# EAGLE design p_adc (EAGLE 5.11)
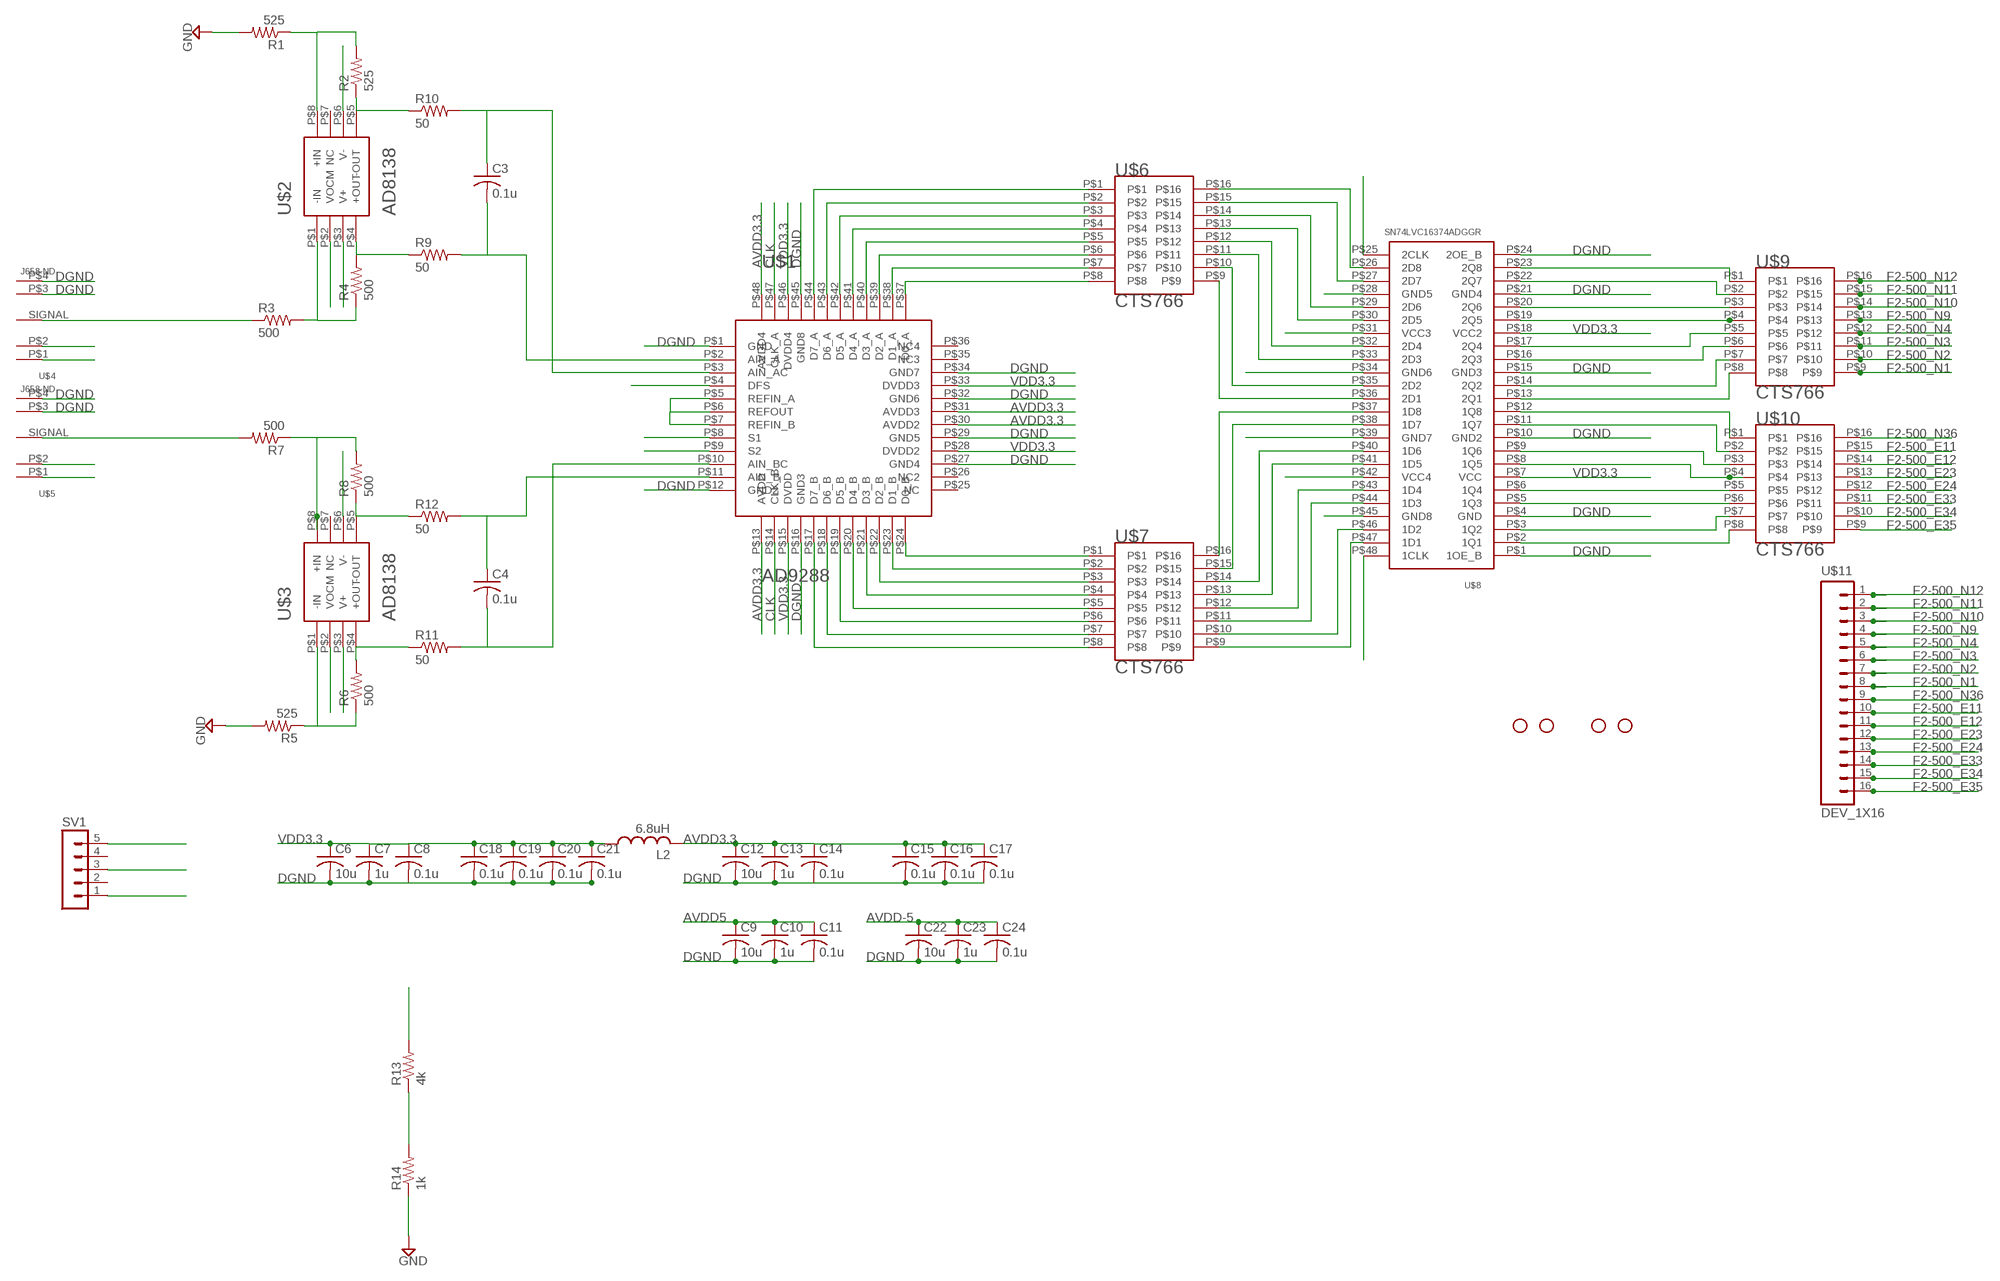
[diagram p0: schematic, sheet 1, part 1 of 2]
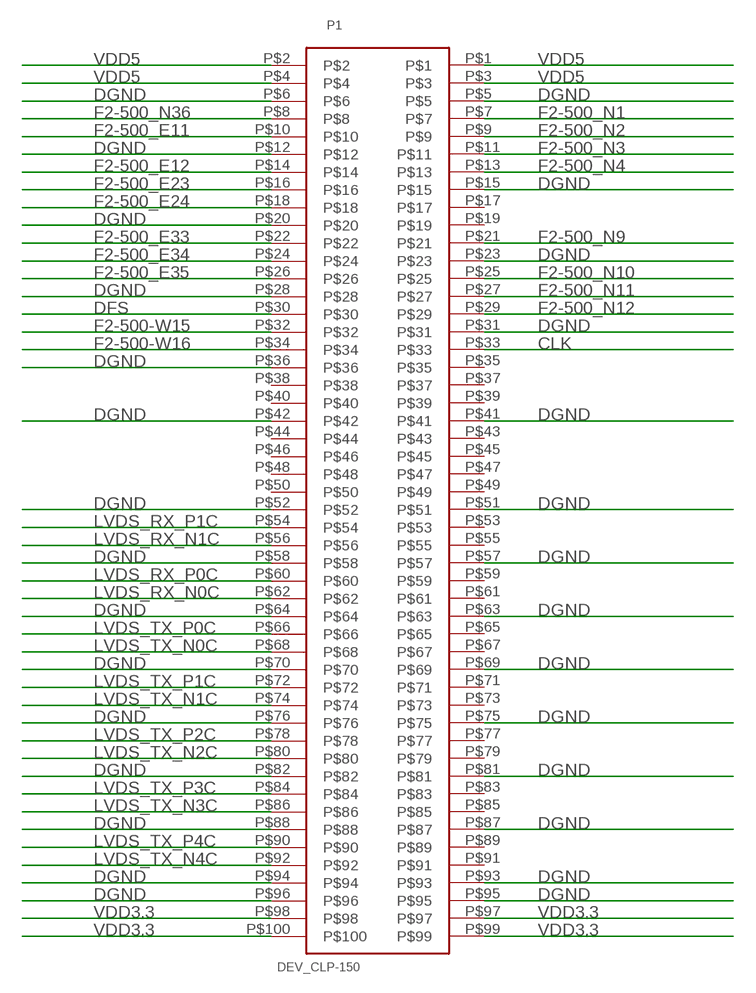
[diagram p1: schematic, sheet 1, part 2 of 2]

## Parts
C3  0.1u  C-USC0603  [C0603]
C4  0.1u  C-USC0603  [C0603]
C6  10u  C-USC0603  [C0603]
C7  1u  C-USC0603  [C0603]
C8  0.1u  C-USC0603  [C0603]
C9  10u  C-USC0603  [C0603]
C10  1u  C-USC0603  [C0603]
C11  0.1u  C-USC0603  [C0603]
C12  10u  C-USC0603  [C0603]
C13  1u  C-USC0603  [C0603]
C14  0.1u  C-USC0603  [C0603]
C15  0.1u  C-USC0603  [C0603]
C16  0.1u  C-USC0603  [C0603]
C17  0.1u  C-USC0603  [C0603]
C18  0.1u  C-USC0603  [C0603]
C19  0.1u  C-USC0603  [C0603]
C20  0.1u  C-USC0603  [C0603]
C21  0.1u  C-USC0603  [C0603]
C22  10u  C-USC0603  [C0603]
C23  1u  C-USC0603  [C0603]
C24  0.1u  C-USC0603  [C0603]
JP1  STAND-OFF  [STAND-OFF]
JP2  STAND-OFF  [STAND-OFF]
JP3  STAND-OFF  [STAND-OFF]
JP4  STAND-OFF  [STAND-OFF]
L2  6.8uH  L-US  [L1210]
P1  DEV_CLP-150  [CLP-150]
R1  525  RESISTOR0603-RES  [0603-RES]
R2  525  RESISTOR0603-RES  [0603-RES]
R3  500  RESISTOR0603-RES  [0603-RES]
R4  500  RESISTOR0603-RES  [0603-RES]
R5  525  RESISTOR0603-RES  [0603-RES]
R6  500  RESISTOR0603-RES  [0603-RES]
R7  500  RESISTOR0603-RES  [0603-RES]
R8  500  RESISTOR0603-RES  [0603-RES]
R9  50  RESISTOR0603-RES  [0603-RES]
R10  50  RESISTOR0603-RES  [0603-RES]
R11  50  RESISTOR0603-RES  [0603-RES]
R12  50  RESISTOR0603-RES  [0603-RES]
R13  4k  RESISTOR0603-RES  [0603-RES]
R14  1k  RESISTOR0603-RES  [0603-RES]
SV1  MA05-1  [MA05-1]
U$1  AD9288  [LQFP(ST-48)]
U$2  AD8138  [MSOP(RM-8)]
U$3  AD8138  [MSOP(RM-8)]
U$4  J658-ND  [SMA-SMD]
U$5  J658-ND  [SMA-SMD]
U$6  CTS766  [16-SOIC]
U$7  CTS766  [16-SOIC]
U$8  SN74LVC16374ADGGR  [TSSOP-48]
U$9  CTS766  [16-SOIC]
U$10  CTS766  [16-SOIC]
U$11  DEV_1X16  [1X16]

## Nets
AVDD3.3: C12.1 C13.1 C14.1 C15.1 C16.1 C17.1 L2.2 U$1.P$13(AVDD) U$1.P$30(AVDD2) U$1.P$31(AVDD3) U$1.P$48(AVDD4)
AVDD5: C9.1 C10.1 C11.1 R13.2 SV1.5 U$2.P$3(V+) U$3.P$3(V+)
AVDD-5: C22.1 C23.1 C24.1 SV1.1 U$2.P$6(V-) U$3.P$6(V-)
CLK: P1.P$33 U$1.P$14(CLK_B) U$1.P$47(CLK_A) U$8.P$25(2CLK) U$8.P$48(1CLK)
DFS: P1.P$30 U$1.P$4(DFS)
DGND: C6.2 C7.2 C8.2 C9.2 C10.2 C11.2 C12.2 C13.2 C14.2 C15.2 C16.2 C17.2 C18.2 C19.2 C20.2 C21.2 C22.2 C23.2 C24.2 P1.P$5 P1.P$6 P1.P$12 P1.P$15 P1.P$20 P1.P$23 P1.P$28 P1.P$31 P1.P$36 P1.P$41 P1.P$42 P1.P$51 P1.P$52 P1.P$57 P1.P$58 P1.P$63 P1.P$64 P1.P$69 P1.P$70 P1.P$75 P1.P$76 P1.P$81 P1.P$82 P1.P$87 P1.P$88 P1.P$93 P1.P$94 P1.P$95 P1.P$96 R1.2 R5.2 R14.1 SV1.3 U$1.P$1(GND) U$1.P$9(S2) U$1.P$12(GND2) U$1.P$16(GND3) U$1.P$27(GND4) U$1.P$29(GND5) U$1.P$32(GND6) U$1.P$34(GND7) U$1.P$45(GND8) U$4.P$1(GND1) U$4.P$2(GND2) U$4.P$3(GND3) U$4.P$4(GND4) U$5.P$1(GND1) U$5.P$2(GND2) U$5.P$3(GND3) U$5.P$4(GND4) U$8.P$1(1OE_B) U$8.P$4(GND) U$8.P$10(GND2) U$8.P$15(GND3) U$8.P$21(GND4) U$8.P$24(2OE_B) U$8.P$28(GND5) U$8.P$34(GND6) U$8.P$39(GND7) U$8.P$45(GND8) ; supply symbol labelled GND
F2-500-W15: P1.P$32
F2-500-W16: P1.P$34
F2-500_E11: P1.P$10 U$10.P$15 U$11.10
F2-500_E12: P1.P$14 U$10.P$14 U$11.11
F2-500_E23: P1.P$16 U$10.P$13 U$11.12
F2-500_E24: P1.P$18 U$10.P$12 U$11.13
F2-500_E33: P1.P$22 U$10.P$11 U$11.14
F2-500_E34: P1.P$24 U$10.P$10 U$11.15
F2-500_E35: P1.P$26 U$10.P$9 U$11.16
F2-500_N1: P1.P$7 U$9.P$9 U$11.8
F2-500_N2: P1.P$9 U$9.P$10 U$11.7
F2-500_N3: P1.P$11 U$9.P$11 U$11.6
F2-500_N4: P1.P$13 U$9.P$12 U$11.5
F2-500_N9: P1.P$21 U$9.P$13 U$11.4
F2-500_N10: P1.P$25 U$9.P$14 U$11.3
F2-500_N11: P1.P$27 U$9.P$15 U$11.2
F2-500_N12: P1.P$29 U$9.P$16 U$11.1
F2-500_N36: P1.P$8 U$10.P$16 U$11.9
LVDS_RX_N0C: P1.P$62
LVDS_RX_N1C: P1.P$56
LVDS_RX_P0C: P1.P$60
LVDS_RX_P1C: P1.P$54
LVDS_TX_N0C: P1.P$68
LVDS_TX_N1C: P1.P$74
LVDS_TX_N2C: P1.P$80
LVDS_TX_N3C: P1.P$86
LVDS_TX_N4C: P1.P$92
LVDS_TX_P0C: P1.P$66
LVDS_TX_P1C: P1.P$72
LVDS_TX_P2C: P1.P$78
LVDS_TX_P3C: P1.P$84
LVDS_TX_P4C: P1.P$90
N$1: R3.2 R4.1 U$2.P$1(-IN)
N$2: R4.2 R9.1 U$2.P$4(+OUT)
N$3: R1.1 R2.2 U$2.P$8(+IN)
N$4: R2.1 R10.1 U$2.P$5(-OUT)
N$5: R6.2 R11.1 U$3.P$4(+OUT)
N$6: R5.1 R6.1 U$3.P$1(-IN)
N$7: R8.1 R12.1 U$3.P$5(-OUT)
N$8: R7.1 R8.2 U$3.P$8(+IN)
N$11: C4.1 R12.2 U$1.P$11(AIN_B)
N$12: C4.2 R11.2 U$1.P$10(AIN_BC)
N$13: R3.1 U$4.SIGNAL
N$14: C3.1 R10.2 U$1.P$3(AIN_AC)
N$15: U$1.P$5(REFIN_A) U$1.P$6(REFOUT) U$1.P$7(REFIN_B)
N$16: U$1.P$24(D0_B) U$7.P$1
N$17: U$1.P$23(D1_B) U$7.P$2
N$18: U$1.P$22(D2_B) U$7.P$3
N$19: U$1.P$21(D3_B) U$7.P$4
N$20: U$1.P$20(D4_B) U$7.P$5
N$21: U$1.P$19(D5_B) U$7.P$6
N$22: U$1.P$18(D6_B) U$7.P$7
N$23: U$1.P$17(D7_B) U$7.P$8
N$24: U$1.P$37(D0_A) U$6.P$8
N$25: U$1.P$38(D1_A) U$6.P$7
N$26: U$1.P$39(D2_A) U$6.P$6
N$27: U$1.P$40(D3_A) U$6.P$5
N$28: U$1.P$41(D4_A) U$6.P$4
N$29: U$1.P$42(D5_A) U$6.P$3
N$30: U$1.P$43(D6_A) U$6.P$2
N$31: U$1.P$44(D7_A) U$6.P$1
N$32: C3.2 R9.2 U$1.P$2(AIN_A)
N$33: R7.2 U$5.SIGNAL
N$34: U$8.P$13(2Q1) U$9.P$8
N$35: U$6.P$9 U$8.P$36(2D1)
N$36: U$6.P$10 U$8.P$35(2D2)
N$37: U$6.P$11 U$8.P$33(2D3)
N$38: U$6.P$12 U$8.P$32(2D4)
N$39: U$6.P$13 U$8.P$30(2D5)
N$40: U$6.P$14 U$8.P$29(2D6)
N$41: U$6.P$15 U$8.P$27(2D7)
N$42: U$6.P$16 U$8.P$26(2D8)
N$43: U$7.P$16 U$8.P$37(1D8)
N$44: U$7.P$15 U$8.P$38(1D7)
N$45: U$7.P$14 U$8.P$40(1D6)
N$46: U$7.P$13 U$8.P$41(1D5)
N$47: U$7.P$12 U$8.P$43(1D4)
N$48: U$7.P$11 U$8.P$44(1D3)
N$49: U$7.P$10 U$8.P$46(1D2)
N$50: U$7.P$9 U$8.P$47(1D1)
N$51: U$8.P$14(2Q2) U$9.P$7
N$52: U$8.P$16(2Q3) U$9.P$6
N$53: U$8.P$17(2Q4) U$9.P$5
N$54: U$8.P$19(2Q5) U$9.P$4
N$55: U$8.P$20(2Q6) U$9.P$3
N$56: U$8.P$23(2Q8) U$9.P$1
N$57: U$8.P$22(2Q7) U$9.P$2
N$58: U$8.P$2(1Q1) U$10.P$8
N$59: U$8.P$3(1Q2) U$10.P$7
N$60: U$8.P$5(1Q3) U$10.P$6
N$61: U$8.P$6(1Q4) U$10.P$5
N$62: U$8.P$12(1Q8) U$10.P$1
N$63: U$8.P$11(1Q7) U$10.P$2
N$64: U$8.P$9(1Q6) U$10.P$3
N$65: U$8.P$8(1Q5) U$10.P$4
VCOM: R13.1 R14.2 U$2.P$2(VOCM) U$3.P$2(VOCM)
VDD3.3: C6.1 C7.1 C8.1 C18.1 C19.1 C20.1 C21.1 L2.1 P1.P$97 P1.P$98 P1.P$99 P1.P$100 U$1.P$8(S1) U$1.P$15(DVDD) U$1.P$28(DVDD2) U$1.P$33(DVDD3) U$1.P$46(DVDD4) U$8.P$7(VCC) U$8.P$18(VCC2) U$8.P$31(VCC3) U$8.P$42(VCC4)
VDD5: P1.P$1 P1.P$2 P1.P$3 P1.P$4
Unconnected: P1.P$17 P1.P$19 P1.P$35 P1.P$37 P1.P$38 P1.P$39 P1.P$40 P1.P$43 P1.P$44 P1.P$45 P1.P$46 P1.P$47 P1.P$48 P1.P$49 P1.P$50 P1.P$53 P1.P$55 P1.P$59 P1.P$61 P1.P$65 P1.P$67 P1.P$71 P1.P$73 P1.P$77 P1.P$79 P1.P$83 P1.P$85 P1.P$89 P1.P$91 SV1.2 SV1.4 U$1.P$25(NC) U$1.P$26(NC2) U$1.P$35(NC3) U$1.P$36(NC4) U$2.P$7(NC) U$3.P$7(NC)

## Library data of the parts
C3 C4 C6-C24 = rcl:C-US: CAPACITOR, American symbol
JP1-JP4 = SparkFun:STAND-OFF: Stand Off
L2 = sam:L-US: INDUCTOR, American symbol
P1 = EECS370:DEV_CLP-150
R1-R14 = SparkFun:RESISTOR: Resistor
SV1 = con-lstb:MA05-1: PIN HEADER; OC_FARNELL: unknown; OC_NEWARK: unknown
U$1 = sam:AD9288
U$2 U$3 = sam:AD8138
U$4 U$5 = sam:J658-ND
U$6 U$7 U$9 U$10 = sam:CTS766
U$8 = sam:SN74LVC16374ADGGR
U$11 = EECS370:DEV_1X16

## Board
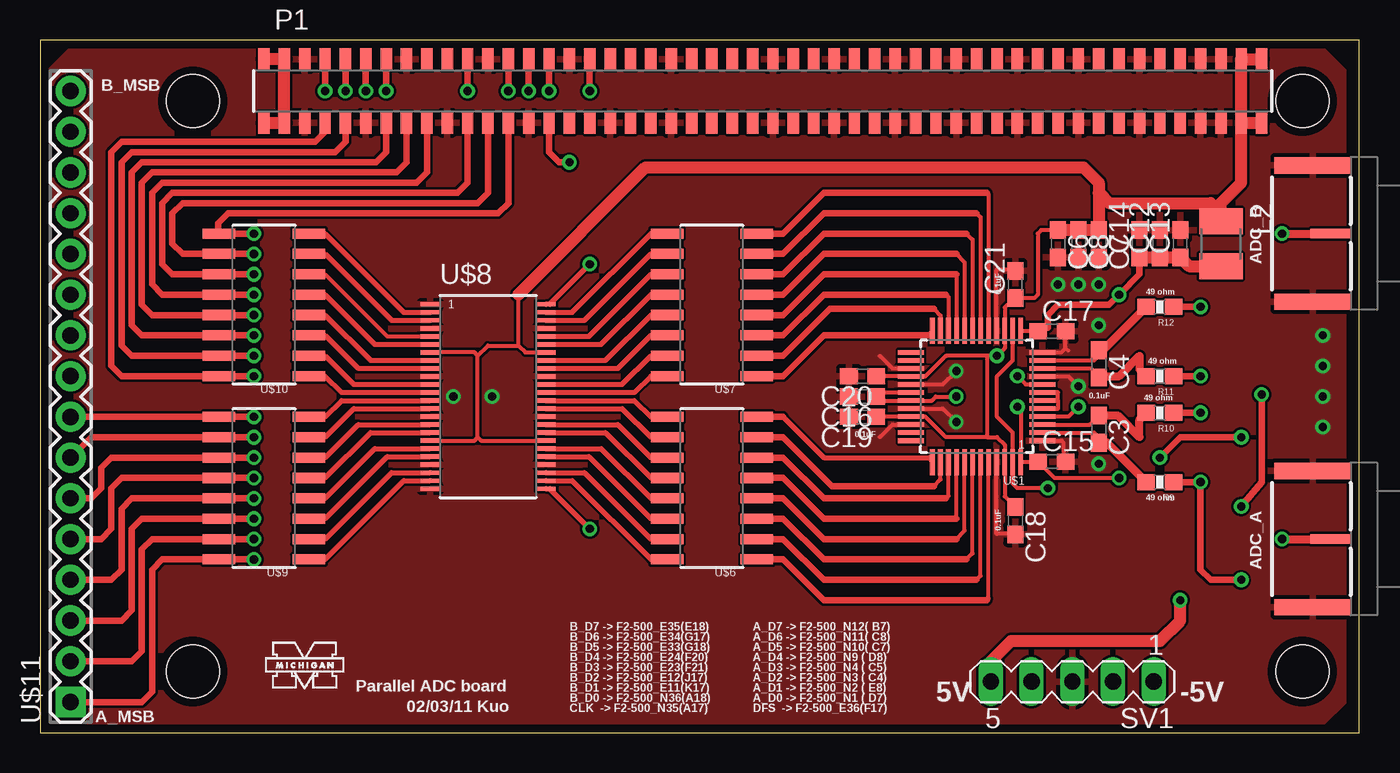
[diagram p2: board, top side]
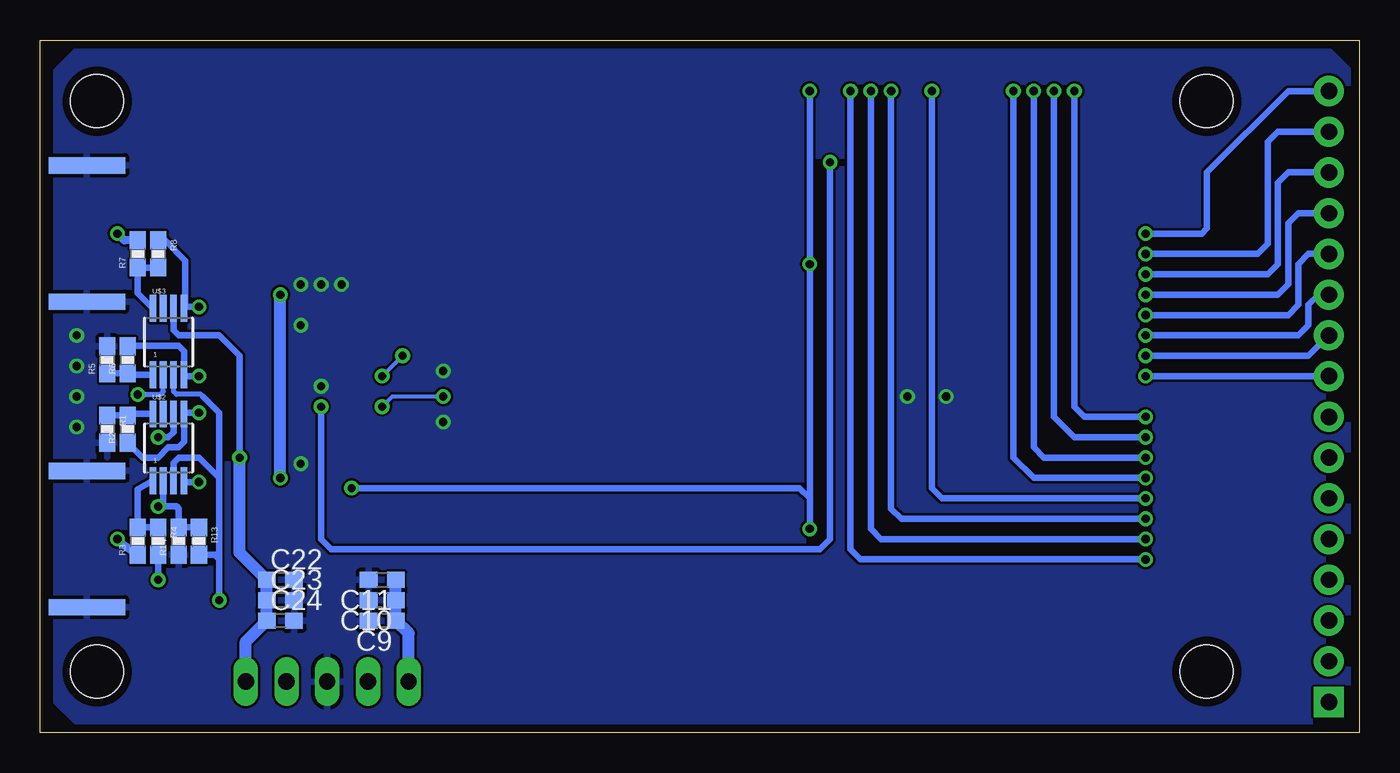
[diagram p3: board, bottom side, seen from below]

Size 82.3 x 43.18 mm. Coordinates in mm from the lower left corner, seen from the top.
Outline: 0,0 82.3,0 82.3,43.18 0,43.18 0,0
Copper layers (1*16): Top 0.0178mm / dielectric 1.4986mm / Bottom 0.0178mm
Design rules "SSC-EAGLE-2Lyr_v1.0.0.3": minimum track width 6mil, minimum drill 14mil, track to track 6mil, track to pad 6mil, pad to pad 6mil, via to via 6mil, smd to smd 6mil, copper to edge 20mil, drill to drill 16mil, minimum pad ring 8mil, minimum via ring 8mil, stop-mask expansion 3mil, vias tented up to drill 0mil, thermal gap 10mil

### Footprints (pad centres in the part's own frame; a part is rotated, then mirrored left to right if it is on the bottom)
C0603 = smd 1.1 x 1: 1 -0.85,0; 2 0.85,0
STAND-OFF = hole 3.302: 0,0
L1210 = smd 1.6 x 2.7: 1 -1.4,0; 2 1.4,0
CLP-150 = smd 0.711 x 1.35: P$1 -31.115,1.99; P$2 -31.115,-1.99; P$3 -29.845,1.99; P$4 -29.845,-1.99; P$5 -28.575,1.99; P$6 -28.575,-1.99; P$7 -27.305,1.99; P$8 -27.305,-1.99; P$9 -26.035,1.99; P$10 -26.035,-1.99; P$11 -24.765,1.99; P$12 -24.765,-1.99; P$13 -23.495,1.99; P$14 -23.495,-1.99; P$15 -22.225,1.99; P$16 -22.225,-1.99; P$17 -20.955,1.99; P$18 -20.955,-1.99; P$19 -19.685,1.99; P$20 -19.685,-1.99; P$21 -18.415,1.99; P$22 -18.415,-1.99; P$23 -17.145,1.99; P$24 -17.145,-1.99; P$25 -15.875,1.99; P$26 -15.875,-1.99; P$27 -14.605,1.99; P$28 -14.605,-1.99; P$29 -13.335,1.99; P$30 -13.335,-1.99; P$31 -12.065,1.99; P$32 -12.065,-1.99; P$33 -10.795,1.99; P$34 -10.795,-1.99; P$35 -9.525,1.99; P$36 -9.525,-1.99; P$37 -8.255,1.99; P$38 -8.255,-1.99; P$39 -6.985,1.99; P$40 -6.985,-1.99; P$41 -5.715,1.99; P$42 -5.715,-1.99; P$43 -4.445,1.99; P$44 -4.445,-1.99; P$45 -3.175,1.99; P$46 -3.175,-1.99; P$47 -1.905,1.99; P$48 -1.905,-1.99; P$49 -0.635,1.99; P$50 -0.635,-1.99; P$51 0.635,1.99; P$52 0.635,-1.99; P$53 1.905,1.99; P$54 1.905,-1.99; P$55 3.175,1.99; P$56 3.175,-1.99; P$57 4.445,1.99; P$58 4.445,-1.99; P$59 5.715,1.99; P$60 5.715,-1.99; P$61 6.985,1.99; P$62 6.985,-1.99; P$63 8.255,1.99; P$64 8.255,-1.99; P$65 9.525,1.99; P$66 9.525,-1.99; P$67 10.795,1.99; P$68 10.795,-1.99; P$69 12.065,1.99; P$70 12.065,-1.99; P$71 13.335,1.99; P$72 13.335,-1.99; P$73 14.605,1.99; P$74 14.605,-1.99; P$75 15.875,1.99; P$76 15.875,-1.99; P$77 17.145,1.99; P$78 17.145,-1.99; P$79 18.415,1.99; P$80 18.415,-1.99; P$81 19.685,1.99; P$82 19.685,-1.99; P$83 20.955,1.99; P$84 20.955,-1.99; P$85 22.225,1.99; P$86 22.225,-1.99; P$87 23.495,1.99; P$88 23.495,-1.99; P$89 24.765,1.99; P$90 24.765,-1.99; P$91 26.035,1.99; P$92 26.035,-1.99; P$93 27.305,1.99; P$94 27.305,-1.99; P$95 28.575,1.99; P$96 28.575,-1.99; P$97 29.845,1.99; P$98 29.845,-1.99; P$99 31.115,1.99; P$100 31.115,-1.99
0603-RES = smd 1.1 x 1: 1 -0.85,0; 2 0.85,0
MA05-1 = drill 1.016 long: 1 -5.08,0; 2 -2.54,0; 3 0,0; 4 2.54,0; 5 5.08,0
LQFP(ST-48) = smd 1.6 x 0.3: P$1 -4.1,2.75; P$2 -4.1,2.25; P$3 -4.1,1.75; P$4 -4.1,1.25; P$5 -4.1,0.75; P$6 -4.1,0.25; P$7 -4.1,-0.25; P$8 -4.1,-0.75; P$9 -4.1,-1.25; P$10 -4.1,-1.75; P$11 -4.1,-2.25; P$12 -4.1,-2.75; P$25 4.1,-2.75; P$26 4.1,-2.25; P$27 4.1,-1.75; P$28 4.1,-1.25; P$29 4.1,-0.75; P$30 4.1,-0.25; P$31 4.1,0.25; P$32 4.1,0.75; P$33 4.1,1.25; P$34 4.1,1.75; P$35 4.1,2.25; P$36 4.1,2.75 | smd 0.3 x 1.6: P$13 -2.75,-4.1; P$14 -2.25,-4.1; P$15 -1.75,-4.1; P$16 -1.25,-4.1; P$17 -0.75,-4.1; P$18 -0.25,-4.1; P$19 0.25,-4.1; P$20 0.75,-4.1; P$21 1.25,-4.1; P$22 1.75,-4.1; P$23 2.25,-4.1; P$24 2.75,-4.1; P$37 2.75,4.1; P$38 2.25,4.1; P$39 1.75,4.1; P$40 1.25,4.1; P$41 0.75,4.1; P$42 0.25,4.1; P$43 -0.25,4.1; P$44 -0.75,4.1; P$45 -1.25,4.1; P$46 -1.75,4.1; P$47 -2.25,4.1; P$48 -2.75,4.1
MSOP(RM-8) = smd 0.41 x 1.68: P$1 -0.975,-2.085; P$2 -0.325,-2.085; P$3 0.325,-2.085; P$4 0.975,-2.085; P$5 0.975,2.085; P$6 0.325,2.085; P$7 -0.325,2.085; P$8 -0.975,2.085
SMA-SMD = smd 1.02 x 4.75: P$1 -4.25,0; P$2 4.25,0 | smd 1.02 x 4.75 bottom: P$3 4.25,0; P$4 -4.25,0 | smd 0.6 x 2.5: SIGNAL 0,1.125
16-SOIC = smd 2.03 x 0.63: P$1 -2.8,4.445; P$2 -2.8,3.175; P$3 -2.8,1.905; P$4 -2.8,0.635; P$5 -2.8,-0.635; P$6 -2.8,-1.905; P$7 -2.8,-3.175; P$8 -2.8,-4.445; P$9 2.8,-4.445; P$10 2.8,-3.175; P$11 2.8,-1.905; P$12 2.8,-0.635; P$13 2.8,0.635; P$14 2.8,1.905; P$15 2.8,3.175; P$16 2.8,4.445
TSSOP-48 = smd 1.2 x 0.27: P$1 -3.6,5.75; P$2 -3.6,5.25; P$3 -3.6,4.75; P$4 -3.6,4.25; P$5 -3.6,3.75; P$6 -3.6,3.25; P$7 -3.6,2.75; P$8 -3.6,2.25; P$9 -3.6,1.75; P$10 -3.6,1.25; P$11 -3.6,0.75; P$12 -3.6,0.25; P$13 -3.6,-0.25; P$14 -3.6,-0.75; P$15 -3.6,-1.25; P$16 -3.6,-1.75; P$17 -3.6,-2.25; P$18 -3.6,-2.75; P$19 -3.6,-3.25; P$20 -3.6,-3.75; P$21 -3.6,-4.25; P$22 -3.6,-4.75; P$23 -3.6,-5.25; P$24 -3.6,-5.75; P$25 3.6,-5.75; P$26 3.6,-5.25; P$27 3.6,-4.75; P$28 3.6,-4.25; P$29 3.6,-3.75; P$30 3.6,-3.25; P$31 3.6,-2.75; P$32 3.6,-2.25; P$33 3.6,-1.75; P$34 3.6,-1.25; P$35 3.6,-0.75; P$36 3.6,-0.25; P$37 3.6,0.25; P$38 3.6,0.75; P$39 3.6,1.25; P$40 3.6,1.75; P$41 3.6,2.25; P$42 3.6,2.75; P$43 3.6,3.25; P$44 3.6,3.75; P$45 3.6,4.25; P$46 3.6,4.75; P$47 3.6,5.25; P$48 3.6,5.75
1X16 = drill 1.016 pad 1.88 square: 1 -19.05,0 | drill 1.016 pad 1.88 round: 2 -16.51,0; 3 -13.97,0; 4 -11.43,0; 5 -8.89,0; 6 -6.35,0; 7 -3.81,0; 8 -1.27,0; 9 1.27,0; 10 3.81,0; 11 6.35,0; 12 8.89,0; 13 11.43,0; 14 13.97,0; 15 16.51,0; 16 19.05,0

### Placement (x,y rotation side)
C3  66.04,18.92 270 top
C4  66.04,22.99 270 top
C6  63.5,30.48 270 top
C7  66.04,30.48 270 top
C8  64.77,30.48 270 top
C9  60.96,6.99 180 bottom
C10  60.96,8.26 180 bottom
C11  60.96,9.53 180 bottom
C12  69.85,30.48 90 top
C13  71.12,30.48 90 top
C14  68.58,30.48 90 top
C15  63.12,16.89 0 top
C16  51.31,20.95 180 top
C17  63.12,25.02 0 top
C18  60.83,13.21 270 top
C19  51.31,19.68 180 top
C20  51.31,22.23 180 top
C21  60.83,27.94 90 top
C22  67.31,9.53 0 bottom
C23  67.31,8.26 0 bottom
C24  67.31,6.99 0 bottom
JP1  9.53,39.37 0 top
JP2  9.53,3.81 0 top
JP3  78.74,39.37 0 top
JP4  78.74,3.81 0 top
L2  73.66,30.48 270 top
P1  45.09,40.01 0 top
R1  78.11,18.92 270 bottom
R2  76.83,18.92 90 bottom
R3  76.2,11.94 90 bottom
R4  74.93,11.94 270 bottom
R5  78.11,23.24 90 bottom
R6  76.83,23.24 90 bottom
R7  76.2,29.84 90 bottom
R8  74.93,29.84 270 bottom
R9  69.85,15.62 180 top
R10  69.85,19.94 180 top
R11  69.85,22.23 180 top
R12  69.85,26.54 180 top
R13  72.39,11.94 270 bottom
R14  73.66,11.94 90 bottom
SV1  64.39,3.17 180 top
U$1  58.42,20.95 180 top
U$2  74.3,17.78 0 bottom
U$3  74.3,24.38 0 bottom
U$4  79.38,12.06 270 top
U$5  79.38,31.11 270 top
U$6  41.91,15.24 180 top
U$7  41.91,26.67 180 top
U$8  27.94,20.95 0 top
U$9  13.97,15.24 180 top
U$10  13.97,26.67 180 top
U$11  1.91,20.95 90 top
U$12  [UMICH]  13.97,2.54 0 top

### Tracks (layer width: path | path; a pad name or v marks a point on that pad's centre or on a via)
AVDD3.3  (via drill 0.51)
  Top 0.254: U$1.P$30 52.53,21.2 C16.1 52.53,20.7 U$1.P$31 55.63,20.7 55.88,20.95 v57.15,20.95 | v60.96,20.32 61.17,20.11 U$1.P$48 61.23,16.89 C15.1 63.28,15.88 v67.31,15.88 | C17.1 61.21,25.02 U$1.P$13
  Top 0.406: C14.1 68.58,28.57 v67.31,27.3 66.67,26.67 63.5,26.67 62.87,26.04 62.87,25.23 62.48,25.23 C17.1
  Top 0.762: L2.2 71.67,29.08 C13.1 C12.1 C14.1
  Bottom 0.254: v57.15,20.95 60.33,20.95 v60.96,20.32
  Bottom 0.762: v67.31,15.88 v67.31,27.3
AVDD5  (via drill 0.51)
  Top 0.762: v71.12,8.26 71.12,6.99 69.85,5.71 60.58,5.71 59.31,4.45 SV1.5
  Bottom 0.305: U$3.P$3 73.97,21.27 73.79,21.08 72.26,21.08 72.14,20.95
  Bottom 0.406: 72.14,20.95 71.12,19.94 71.12,15.88 | v71.12,8.26 71.12,10.79 | 71.12,10.79 71.12,15.88 | 71.12,15.88 72.39,17.14 73.66,17.14 73.97,16.84 U$2.P$3 | R13.2 71.41,11.09 71.12,10.79
  Bottom 0.762: C11.1 C10.1 C9.1 59.31,6.18 SV1.5
AVDD-5  (via drill 0.51)
  Top 0.406: v74.93,18.41 71.12,18.41 v69.85,17.14
  Bottom 0.406: v69.85,17.14 69.85,23.5 71.12,24.77 73.66,24.77 73.97,25.07 U$3.P$6 | U$2.P$6 73.97,18.74 74.3,18.41 v74.93,18.41
  Bottom 0.762: SV1.1 69.47,5.68 C24.1 C23.1 C22.1 69.85,11.21 v69.85,17.14
CLK  (via drill 0.51)
  Top 0.254: U$1.P$14 60.67,23.2 59.69,22.23 59.69,19.68 60.67,18.7 U$1.P$47 60.67,15.53 60.96,15.24 v62.87,15.24
  Top 0.305: U$8.P$48 31.79,26.7 v34.29,29.21 | U$8.P$25 31.79,15.21 v34.29,12.7
  Top 0.406: v34.29,40.01 P1.P$33
  Bottom 0.406: v34.29,40.01 v34.29,29.21 34.29,14.61 | v34.29,12.7 34.29,14.61 | v62.87,15.24 34.92,15.24 34.29,14.61
DFS  (via drill 0.51)
  Top 0.254: U$1.P$4 64.16,19.7 v64.77,20.32
  Top 0.406: P1.P$30 31.75,36.2 32.38,35.56 v33.02,35.56
  Bottom 0.406: v33.02,35.56 33.02,12.06 33.66,11.43 64.14,11.43 64.77,12.06 v64.77,20.32
DGND  (via drill 0.51)
  Top 0.254: U$1.P$45 59.67,12.4 59.69,12.38 60.81,12.38 C18.2 | U$1.P$1 63.71,18.2 63.82,18.1 63.82,17.04 C15.2 | U$1.P$32 56.31,20.2 v57.15,19.37 | U$1.P$29 56.31,21.7 v57.15,22.54 | 53.49,19.2 U$1.P$34 53.18,19.2 52.39,18.41 | 63.97,23.98 C17.2 | 63.97,23.98 64.14,23.81 | U$1.P$12 63.7,23.7 63.97,23.98 | U$1.P$16 59.67,28.87 59.69,28.89 60.73,28.89 C21.2 | U$1.P$9 64.16,22.2 v64.77,21.59 | U$1.P$27 53.18,22.7 52.39,23.5
  other vias: 63.5,27.94 64.77,27.94 66.04,27.94 66.04,16.76 66.04,25.4 28.19,20.95 25.78,20.95 80.01,24.77 80.01,22.86 80.01,20.95 80.01,19.05
  pour Top: 1.91,42.55 0.64,41.27 0.64,1.91 1.91,0.64 80.01,0.64 81.28,1.91 81.28,41.27 80.01,42.55
  pour Bottom: 1.91,42.55 0.64,41.27 0.64,1.91 1.91,0.64 80.01,0.64 81.28,1.91 81.28,41.27 80.01,42.55
F2-500_E11  (via drill 0.51)
  Top 0.406: P1.P$10 19.05,36.83 18.41,36.2 5.71,36.2 5.08,35.56 5.08,24.13 5.71,23.5 U$10.P$15 v13.34,23.5
  Bottom 0.406: U$11.10 3.17,23.5 v13.34,23.5
F2-500_E12  (via drill 0.51)
  Top 0.406: P1.P$14 21.59,36.2 20.95,35.56 6.35,35.56 5.71,34.92 5.71,25.4 6.35,24.77 U$10.P$14 v13.34,24.77
  Bottom 0.406: U$11.11 2.54,27.3 3.17,26.67 3.17,25.4 3.81,24.77 v13.34,24.77
F2-500_E23  (via drill 0.51)
  Top 0.406: P1.P$16 22.86,35.56 22.23,34.92 6.99,34.92 6.35,34.29 6.35,26.67 6.99,26.04 U$10.P$13 v13.34,26.04
  Bottom 0.406: U$11.12 3.17,29.84 3.81,29.21 3.81,26.67 4.45,26.04 v13.34,26.04
F2-500_E24  (via drill 0.51)
  Top 0.406: P1.P$18 24.13,34.92 23.5,34.29 7.62,34.29 6.99,33.66 6.99,27.94 7.62,27.3 U$10.P$12 v13.34,27.3
  Bottom 0.406: U$11.13 3.81,32.38 4.45,31.75 4.45,27.94 5.08,27.3 v13.34,27.3
F2-500_E33  (via drill 0.51)
  Top 0.406: P1.P$22 26.67,34.29 26.04,33.66 8.26,33.66 7.62,33.02 7.62,29.21 8.26,28.57 U$10.P$11 v13.34,28.57
  Bottom 0.406: U$11.14 4.45,34.92 5.08,34.29 5.08,29.21 5.71,28.57 v13.34,28.57
F2-500_E34  (via drill 0.51)
  Top 0.406: P1.P$24 27.94,33.66 27.3,33.02 8.89,33.02 8.26,32.38 8.26,30.48 8.89,29.84 U$10.P$10 v13.34,29.84
  Bottom 0.406: U$11.15 5.08,37.47 5.71,36.83 5.71,30.48 6.35,29.84 v13.34,29.84
F2-500_E35  (via drill 0.51)
  Top 0.406: P1.P$26 29.21,33.02 28.57,32.38 11.75,32.38 11.11,31.75 11.11,31.17 U$10.P$9 v13.34,31.11
  Bottom 0.406: U$11.16 4.45,40.01 9.53,34.92 9.53,31.43 9.84,31.11 v13.34,31.11
F2-500_N1  (via drill 0.51)
  Top 0.406: U$11.8 U$9.P$9 v13.34,19.68 | v17.78,40.01 P1.P$7
  Bottom 0.406: v17.78,40.01 17.78,20.32 17.14,19.68 v13.34,19.68
F2-500_N2  (via drill 0.51)
  Top 0.406: U$11.7 3.17,18.41 U$9.P$10 v13.34,18.41 | v19.05,40.01 P1.P$9
  Bottom 0.406: v19.05,40.01 19.05,19.68 17.78,18.41 v13.34,18.41
F2-500_N3  (via drill 0.51)
  Top 0.406: U$11.6 3.17,14.61 3.81,15.24 3.81,16.51 4.45,17.14 U$9.P$11 v13.34,17.14 | v20.32,40.01 P1.P$11
  Bottom 0.406: v20.32,40.01 20.32,17.78 19.68,17.14 v13.34,17.14
F2-500_N4  (via drill 0.51)
  Top 0.406: U$11.5 3.81,12.06 4.45,12.7 4.45,15.24 5.08,15.88 U$9.P$12 v13.34,15.88 | v21.59,40.01 P1.P$13
  Bottom 0.406: v21.59,40.01 21.59,17.14 20.32,15.88 v13.34,15.88
F2-500_N9  (via drill 0.51)
  Top 0.406: U$11.4 4.45,9.53 5.08,10.16 5.08,13.97 5.71,14.61 U$9.P$13 v13.34,14.61 | v26.67,40.01 P1.P$21
  Bottom 0.406: v26.67,40.01 26.67,15.24 26.04,14.61 v13.34,14.61
F2-500_N10  (via drill 0.51)
  Top 0.406: U$11.3 5.08,6.99 5.71,7.62 5.71,12.7 6.35,13.34 U$9.P$14 v13.34,13.34 | v29.21,40.01 P1.P$25
  Bottom 0.406: v29.21,40.01 29.21,13.97 28.57,13.34 v13.34,13.34
F2-500_N11  (via drill 0.51)
  Top 0.406: U$11.2 5.71,4.45 6.35,5.08 6.35,11.43 6.99,12.06 U$9.P$15 v13.34,12.06 | v30.48,40.01 P1.P$27
  Bottom 0.406: v30.48,40.01 30.48,12.7 29.84,12.06 v13.34,12.06
F2-500_N12  (via drill 0.51)
  Top 0.406: U$11.1 6.35,1.91 6.99,2.54 6.99,10.16 7.62,10.79 U$9.P$16 v13.34,10.79 | v31.75,40.01 P1.P$29
  Bottom 0.406: v31.75,40.01 31.75,11.43 31.11,10.79 v13.34,10.79
F2-500_N36  (via drill 0.51)
  Top 0.406: P1.P$8 17.78,37.47 17.14,36.83 5.08,36.83 4.45,36.2 4.45,22.86 5.08,22.23 U$10.P$16 v13.34,22.23
  Bottom 0.406: U$11.9 v13.34,22.23
N$1
  Bottom 0.406: R4.1 R3.2 76.2,15.18 U$2.P$1
N$2  (via drill 0.51)
  Top 0.406: R9.1 v72.39,15.62 72.39,10.16 73.03,9.53 v74.93,9.53
  Bottom 0.406: v74.93,9.53 R4.2 | v72.39,15.62 73.25,15.62 U$2.P$4
N$3
  Bottom 0.406: R2.2 76.8,19.81 | R2.2 R1.1 | U$2.P$8 76.74,19.86 R2.2
N$4  (via drill 0.51)
  Top 0.406: R10.1 v72.39,19.94
  Bottom 0.406: v72.39,19.94 73.25,19.94 U$2.P$5 73.32,18.12 73.66,17.78 74.3,17.78 74.93,17.14 75.91,17.14 R2.1
N$5  (via drill 0.51)
  Top 0.406: R11.1 v72.39,22.23
  Bottom 0.406: v72.39,22.23 73.25,22.23 U$3.P$4 73.32,23.79 73.66,24.13 76.8,24.13 R6.2
N$6
  Bottom 0.406: R6.1 76.79,22.44 | R6.1 R5.1 | U$3.P$1 76.74,22.3 R6.1
N$7  (via drill 0.51)
  Top 0.406: R12.1 v72.39,26.54
  Bottom 0.406: R8.1 74.51,30.7 73.25,29.43 73.25,26.54 | v72.39,26.54 73.25,26.54 | 73.25,26.54 U$3.P$5
N$8
  Bottom 0.406: R8.2 R7.1 76.2,27.4 U$3.P$8
N$11
  Top 0.254: 66.29,23.84 C4.1 66.04,23.5 65.75,23.2 U$1.P$11
  Top 0.508: 66.29,23.84 R12.2
N$12
  Top 0.254: 66,22.23 C4.2 66.04,22.23 65.56,22.7 U$1.P$10
  Top 0.508: R11.2 68.58,22.64 68.58,23.5 67.31,22.23 66.13,22.23 C4.2
N$13  (via drill 0.51)
  Top 0.508: v77.47,12.06 U$4.SIGNAL
  Bottom 0.508: R3.1 77.13,11.72 v77.47,12.06
N$14
  Top 0.254: 65.83,19.68 C3.1 65.47,19.2 U$1.P$3
  Top 0.508: C3.1 67.22,19.77 68.58,18.41 68.58,19.52 R10.2
N$15
  Top 0.254: 63.5,20.7 U$1.P$6 | U$1.P$7 63.5,21.2 63.5,20.7 | U$1.P$5 63.51,20.2 63.51,20.7 63.5,20.7
N$16
  Top 0.305: 55.48,24.77 U$1.P$24
  Top 0.406: U$7.P$1 46.35,22.23 48.9,24.77 55.48,24.77
N$17
  Top 0.254: U$1.P$23 56.17,26 55.75,26.42
  Top 0.406: U$7.P$2 46.35,23.5 49.28,26.42 55.75,26.42
N$18
  Top 0.254: U$1.P$22 56.67,27.15 56.52,27.3
  Top 0.406: U$7.P$3 46.35,24.77 48.9,27.3 56.52,27.3
N$19
  Top 0.254: U$1.P$21 57.17,28.55 57.15,28.57
  Top 0.406: U$7.P$4 46.35,26.04 48.9,28.57 57.15,28.57
N$20
  Top 0.254: U$1.P$20 57.67,29.32 57.15,29.84
  Top 0.406: U$7.P$5 46.35,27.3 48.9,29.84 57.15,29.84
N$21
  Top 0.254: U$1.P$19 58.17,30.73 57.78,31.11
  Top 0.406: U$7.P$6 46.35,28.57 48.9,31.11 57.78,31.11
N$22
  Top 0.254: U$1.P$18 58.67,32.13 58.42,32.38
  Top 0.406: U$7.P$7 46.35,29.84 48.9,32.38 58.42,32.38
N$23
  Top 0.254: U$1.P$17 59.17,33.54 59.05,33.66
  Top 0.406: U$7.P$8 46.35,31.11 48.9,33.66 59.05,33.66
N$24
  Top 0.305: 46.35,19.68 48.9,17.14 55.48,17.14 U$1.P$37
  Top 0.406: U$6.P$8 46.35,19.68
N$25
  Top 0.254: U$1.P$38 56.17,15.78 55.75,15.37
  Top 0.406: U$6.P$7 46.35,18.41 49.4,15.37 55.75,15.37
N$26
  Top 0.254: U$1.P$39 56.67,14.76 56.52,14.61
  Top 0.406: U$6.P$6 46.35,17.14 48.9,14.61 56.52,14.61
N$27
  Top 0.254: U$1.P$40 57.17,13.36 57.15,13.34
  Top 0.406: U$6.P$5 46.35,15.88 48.9,13.34 57.15,13.34
N$28
  Top 0.254: U$1.P$41 57.67,12.59 57.15,12.06
  Top 0.406: U$6.P$4 46.35,14.61 48.9,12.06 57.15,12.06
N$29
  Top 0.254: U$1.P$42 58.17,11.18 57.78,10.79
  Top 0.406: U$6.P$3 46.35,13.34 48.9,10.79 57.78,10.79
N$30
  Top 0.254: U$1.P$43 58.67,9.78 58.42,9.53
  Top 0.406: U$6.P$2 46.35,12.06 48.9,9.53 58.42,9.53
N$31
  Top 0.254: U$1.P$44 59.17,8.37 59.05,8.26
  Top 0.406: U$6.P$1 46.35,10.79 48.9,8.26 59.05,8.26
N$32
  Top 0.254: 65.83,18.41 C3.2 66.04,18.41 65.75,18.7 U$1.P$2
  Top 0.508: C3.2 66.55,18.07 R9.2
N$33  (via drill 0.51)
  Top 0.508: v77.47,31.11 U$5.SIGNAL
  Bottom 0.508: R7.2 77.05,30.7 v77.47,31.11
N$34
  Top 0.305: U$8.P$13 18.8,20.7 17.78,19.68 U$9.P$8
N$35
  Top 0.305: U$8.P$36 37.08,20.7 38.1,19.68 U$6.P$9
N$36
  Top 0.305: U$8.P$35 36.31,20.2 38.1,18.41 U$6.P$10
N$37
  Top 0.305: U$8.P$33 36.04,19.2 38.1,17.14 U$6.P$11
N$38
  Top 0.305: U$8.P$32 35.27,18.7 38.1,15.88 U$6.P$12
N$39
  Top 0.305: U$8.P$30 35,17.7 38.1,14.61 U$6.P$13
N$40
  Top 0.305: U$8.P$29 34.23,17.2 38.1,13.34 U$6.P$14
N$41
  Top 0.305: U$8.P$27 33.96,16.2 38.1,12.06 U$6.P$15
N$42
  Top 0.305: U$8.P$26 33.19,15.71 38.1,10.79 U$6.P$16
N$43
  Top 0.305: U$8.P$37 37.08,21.2 38.1,22.23 U$7.P$16 39.37,22.23
N$44
  Top 0.305: U$8.P$38 36.31,21.7 38.1,23.5 U$7.P$15
N$45
  Top 0.305: U$8.P$40 36.04,22.7 38.1,24.77 U$7.P$14
N$46
  Top 0.305: U$8.P$41 35.27,23.2 38.1,26.04 U$7.P$13
N$47
  Top 0.305: U$8.P$43 35,24.2 38.1,27.3 U$7.P$12
N$48
  Top 0.305: U$8.P$44 34.23,24.7 38.1,28.57 U$7.P$11
N$49
  Top 0.305: U$8.P$46 33.96,25.7 38.1,29.84 U$7.P$10
N$50
  Top 0.305: U$8.P$47 33.19,26.2 38.1,31.11 U$7.P$9
N$51
  Top 0.305: U$8.P$14 19.57,20.2 17.78,18.41 U$9.P$7
N$52
  Top 0.305: U$8.P$16 19.84,19.2 17.78,17.14 U$9.P$6
N$53
  Top 0.305: U$8.P$17 20.61,18.7 17.78,15.88 U$9.P$5
N$54
  Top 0.305: U$8.P$19 20.88,17.7 17.78,14.61 U$9.P$4
N$55
  Top 0.305: U$8.P$20 21.65,17.2 17.78,13.34 U$9.P$3
N$56
  Top 0.305: U$8.P$23 22.69,15.71 17.78,10.79 U$9.P$1
N$57
  Top 0.305: U$8.P$22 21.92,16.2 17.78,12.06 U$9.P$2
N$58
  Top 0.305: U$8.P$2 22.69,26.2 17.78,31.11 U$10.P$8
N$59
  Top 0.254: U$10.P$7 17.78,29.84
  Top 0.305: U$8.P$3 21.92,25.7 17.78,29.84
N$60
  Top 0.254: U$8.P$5 21.65,24.7 17.78,28.57 U$10.P$6
N$61
  Top 0.305: U$8.P$6 20.88,24.2 17.78,27.3 U$10.P$5 16.51,27.3
N$62
  Top 0.305: U$8.P$12 18.8,21.2 17.78,22.23 U$10.P$1
N$63
  Top 0.305: U$8.P$11 19.57,21.7 17.78,23.5 U$10.P$2
N$64
  Top 0.305: U$8.P$9 19.84,22.7 17.78,24.77 U$10.P$3
N$65
  Top 0.305: U$8.P$8 20.61,23.2 17.78,26.04 U$10.P$4
VCOM  (via drill 0.51)
  Top 0.406: v76.2,21.08 76.2,15.62 v74.93,14.1
  Bottom 0.305: U$3.P$2 74.62,21.27 74.8,21.08 v76.2,21.08
  Bottom 0.406: R13.1 R14.2 73.66,13.97 73.79,14.1 v74.93,14.1 74.62,14.41 U$2.P$2
VDD3.3  (via drill 0.51)
  Top 0.254: U$1.P$8 61.48,21.7 v60.96,22.23 | 29.84,24.13 29.84,27.3 | C19.1 54.4,19.68 U$1.P$33 55.23,19.7 56.52,18.41 59.05,18.41 | 59.05,23.5 v59.69,23.5 60.17,23.98 U$1.P$15 60.17,26.52 60.33,26.67 60.41,26.67 C21.1 62.02,27.09 62.23,27.3 62.23,31.11 62.45,31.33 C6.1 | 59.05,18.41 59.69,18.41 60.17,17.93 U$1.P$46 60.17,14.72 C18.1 | 59.05,23.5 59.05,18.41 | U$8.P$31 27.52,18.2 27.3,18.41 | 29.84,24.13 27.94,24.13 27.3,23.5 | 27.3,18.41 27.3,23.5 | U$8.P$42 30.27,23.7 29.84,24.13 | U$8.P$7 27.09,23.7 27.3,23.5 | U$8.P$18 27.09,18.2 27.3,18.41 | 59.05,23.5 56.52,23.5 55.23,22.2 U$1.P$28 54.3,22.23 C20.1
  Top 0.406: C6.1 63.28,31.11
  Top 0.762: P1.P$99 P1.P$97 P1.P$98 | P1.P$98 P1.P$100 | P1.P$98 74.93,34.29 73.66,33.02 73.66,32.38 | 73.66,32.38 L2.1 | C6.1 C8.1 C7.1 66.04,33.66 | 73.66,32.38 73.03,33.02 66.67,33.02 66.04,33.66 | 66.04,33.66 66.04,34.29 65.09,35.24 37.78,35.24 29.84,27.3
  Bottom 0.254: v59.69,23.5 v60.96,22.23
VDD5
  Top 0.762: P1.P$1 P1.P$3 P1.P$4 P1.P$2

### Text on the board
tPlace: B_MSB | ADC_B | 0.1uF | 49 ohm | 49 ohm | 0.1uF | 49 ohm | 0.1uF | 49 ohm | 0.1uF | ADC_A | B_D6 -> F2-500_E34(G17) | B_D7 -> F2-500_E35(E18) | A_D6 -> F2-500_N11( C8) | A_D7 -> F2-500_N12( B7) | B_D5 -> F2-500_E33(G18) | A_D5 -> F2-500_N10( C7) | B_D3 -> F2-500_E23(F21) | B_D4 -> F2-500_E24(F20) | A_D3 -> F2-500_N4 ( C5) | A_D4 -> F2-500_N9 ( D8) | Parallel ADC board | B_D1 -> F2-500_E11(K17) | B_D2 -> F2-500_E12(J17) | A_D1 -> F2-500_N2 ( E8) | A_D2 -> F2-500_N3 ( C4) | B_D0 -> F2-500_N36(A18) | A_D0 -> F2-500_N1 ( D7) | 5V | -5V | A_MSB | 02/03/11 Kuo | CLK -> F2-500_N35(A17) | DFS -> F2-500_E36(F17)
